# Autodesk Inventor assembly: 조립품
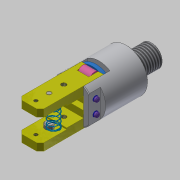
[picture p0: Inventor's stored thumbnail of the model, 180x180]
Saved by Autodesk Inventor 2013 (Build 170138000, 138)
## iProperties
Created: 2019-02
Part Number: 조립품
Document SubType Name: Assembly
Designer: dgall
Author: dgall
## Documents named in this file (11)
- C:\Users\dgall\Desktop\490207V1007\조립품.iam
- C:\Users\dgall\Desktop\490207V1007\본체.ipt
- C:\Users\dgall\Desktop\490207V1007\E-링.ipt
- C:\Users\dgall\Desktop\490207V1007\O-링.ipt
- C:\Users\dgall\Desktop\490207V1007\가이드핀.ipt
- C:\Users\dgall\Desktop\490207V1007\부시.ipt
- C:\Users\dgall\Desktop\490207V1007\스프링.ipt
- C:\Users\dgall\Desktop\490207V1007\평행핀 6x28.ipt
- C:\Users\dgall\Desktop\490207V1007\피스톤.ipt
- C:\Users\dgall\Desktop\490207V1007\핀.ipt
- C:\Users\dgall\Desktop\490207V1007\핑거.ipt
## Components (13 placed, 6 different names)
1. E-링:1
2. O-링:1
3. 가이드핀:1
4. 피스톤:1 — 플러쉬:3
5. 핀:1 — 플러쉬:2
6. 핀:2 — 플러쉬:1
7. 핑거:1
8. 핑거:2
9. 가이드핀:2
10. E-링:2
11. E-링:3
12. E-링:4
13. O-링:2
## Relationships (3: Flush 3)
- 플러쉬:1 [Flush]: 핀:2
- 플러쉬:2 [Flush]: 핀:1
- 플러쉬:3 [Flush]: 피스톤:1
